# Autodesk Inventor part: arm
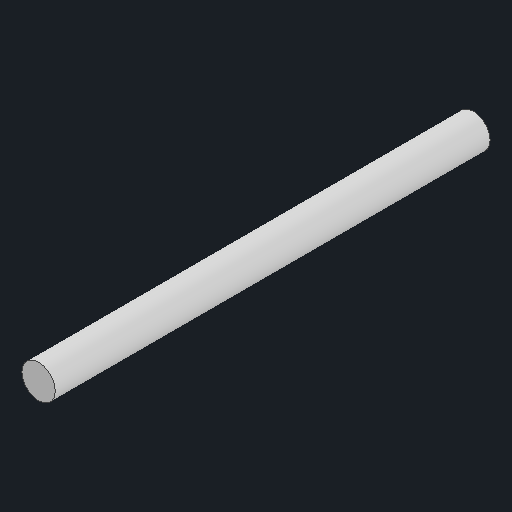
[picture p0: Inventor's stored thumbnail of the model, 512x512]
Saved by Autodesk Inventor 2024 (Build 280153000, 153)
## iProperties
Created: 2023-09
Part Number: arm
Material: Generic
Document SubType Name: Modeling
Designer: mammothbane
Density: 1 g/cm^3
Appearance: Default
Author: mammothbane
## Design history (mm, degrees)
derived "joystick_block.ipt"
feature "arm::joystick_block.ipt" dims "d0" = 10
tag "TaggingFeature1"
node "arm"
